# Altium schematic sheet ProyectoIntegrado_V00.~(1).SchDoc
size A4
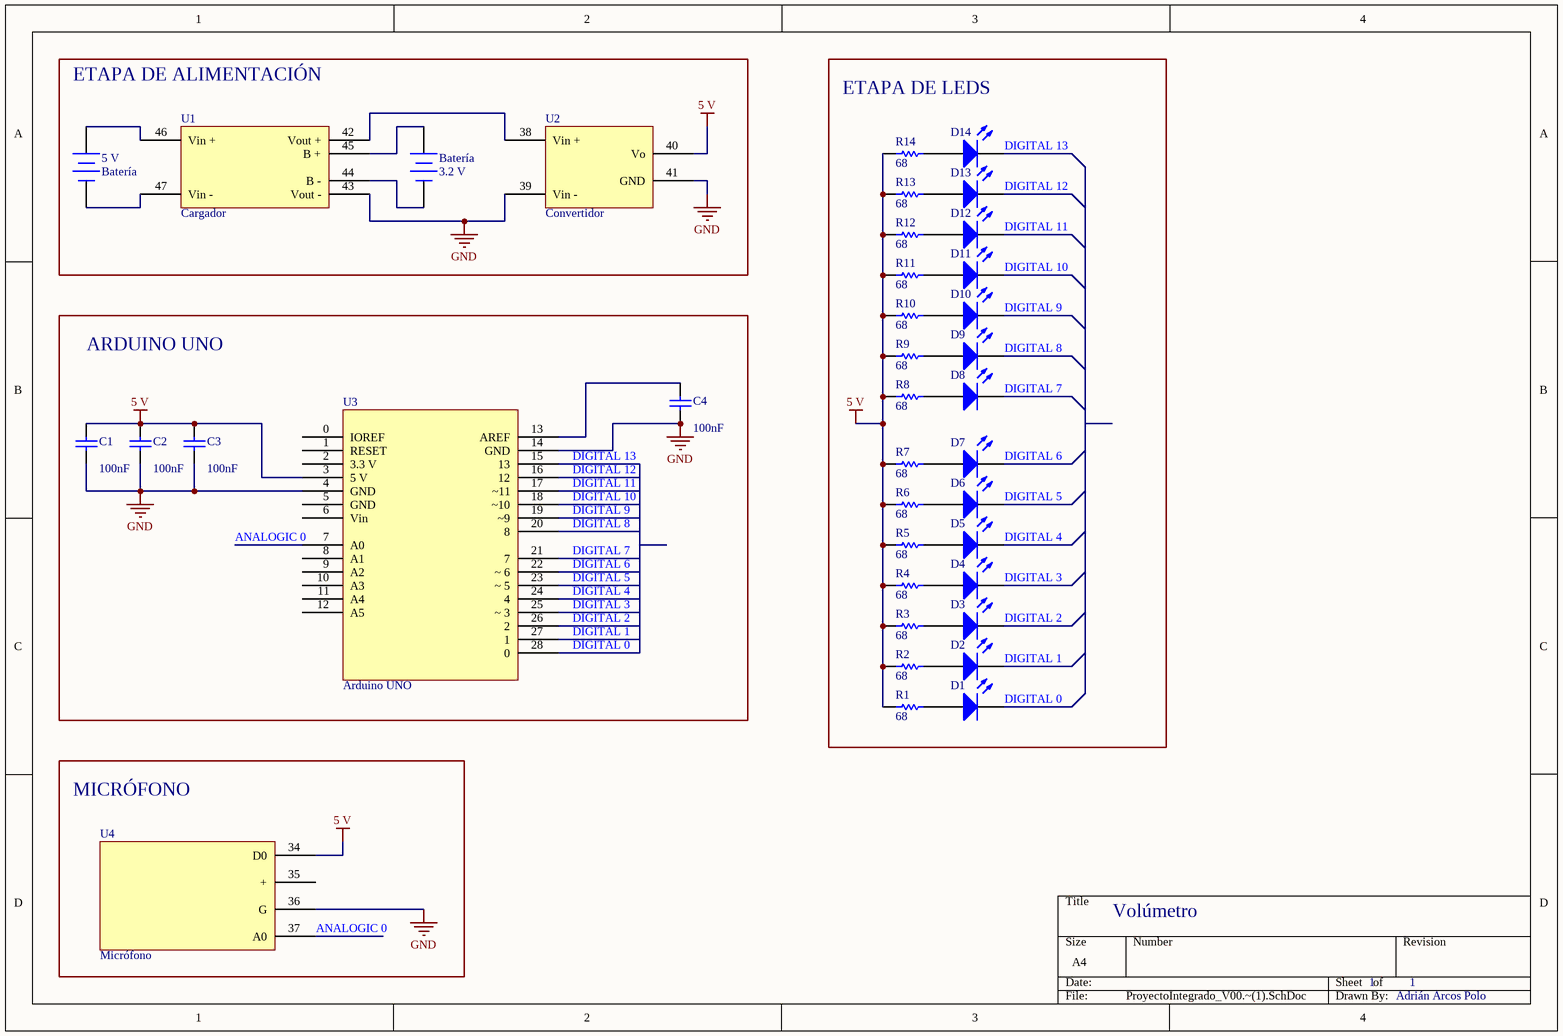
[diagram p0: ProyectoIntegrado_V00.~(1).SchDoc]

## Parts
5_V  Batería  [BAT-2]
Batería  3.2 V  [BAT-2]
C1  value 100nF  [RAD-0.3]  (hidden comment: Cap)
C2  value 100nF  [RAD-0.3]  (hidden comment: Cap)
C3  value 100nF  [RAD-0.3]  (hidden comment: Cap)
C4  value 100nF  [RAD-0.3]  (hidden comment: Cap)
D1  LED3  [3.5X2.8X1.9]  (value not drawn)
D2  LED3  [3.5X2.8X1.9]  (value not drawn)
D3  LED3  [3.5X2.8X1.9]  (value not drawn)
D4  LED3  [3.5X2.8X1.9]  (value not drawn)
D5  LED3  [3.5X2.8X1.9]  (value not drawn)
D6  LED3  [3.5X2.8X1.9]  (value not drawn)
D7  LED3  [3.5X2.8X1.9]  (value not drawn)
D8  LED3  [3.5X2.8X1.9]  (value not drawn)
D9  ED0  [LED-0]  (value not drawn)
D10  LED0  [LED-0]  (value not drawn)
D11  LED0  [LED-0]  (value not drawn)
D12  LED0  [LED-0]  (value not drawn)
D13  LED0  [LED-0]  (value not drawn)
D14  LED0  [LED-0]  (value not drawn)
R1  value 68  [AXIAL-0.3]  (hidden comment: Res1)
R2  value 68  [AXIAL-0.3]  (hidden comment: Res1)
R3  value 68  [AXIAL-0.3]  (hidden comment: Res1)
R4  value 68  [AXIAL-0.3]  (hidden comment: Res1)
R5  value 68  [AXIAL-0.3]  (hidden comment: Res1)
R6  value 68  [AXIAL-0.3]  (hidden comment: Res1)
R7  value 68  [AXIAL-0.3]  (hidden comment: Res1)
R8  value 68  [AXIAL-0.3]  (hidden comment: Res1)
R9  value 68  [AXIAL-0.3]  (hidden comment: Res1)
R10  value 68  [AXIAL-0.3]  (hidden comment: Res1)
R11  value 68  [AXIAL-0.3]  (hidden comment: Res1)
R12  value 68  [AXIAL-0.3]  (hidden comment: Res1)
R13  value 68  [AXIAL-0.3]  (hidden comment: Res1)
R14  value 68  [AXIAL-0.3]  (hidden comment: Res1)
U1  Cargador
U2  Convertidor
U3  Arduino UNO
U4  Micrófono

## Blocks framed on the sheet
ETAPA DE ALIMENTACIÓN: 5_V Batería U1 U2
ETAPA DE LEDS: D1-D14 R1-R14
ARDUINO UNO: C1-C4 U3
MICRÓFONO: U4

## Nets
5 V: C1.2 C2.2 C3.2 R1.2 R2.2 R3.2 R4.2 R5.2 R6.2 R7.2 R8.2 R9.2 R10.2 R11.2 R12.2 R13.2 R14.2 U2.40(Vo) U3.3(5_V) U4.34(D0)
GND: C1.1 C2.1 C3.1 C4.1 U1.43(Vout_-) U2.39(Vin_-) U2.41(GND) U3.4(GND) U3.14(GND) U4.36(G)
ANALOGIC 0: U3.7(A0) U4.37(A0)
DIGITAL 0: D1.2(K) U3.28(0)
DIGITAL 1: D2.2(K) U3.27(1)
DIGITAL 2: D3.2(K) U3.26(2)
DIGITAL 3: D4.2(K) U3.25(~_3)
DIGITAL 4: D5.2(K) U3.24(4)
DIGITAL 5: D6.2(K) U3.23(~_5)
DIGITAL 6: D7.2(K) U3.22(~_6)
DIGITAL 7: D8.2(K) U3.21(7)
DIGITAL 8: D9.2(K) U3.20(8)
DIGITAL 9: D10.2(K) U3.19(~9)
DIGITAL 10: D11.2(K) U3.18(~10)
DIGITAL 11: D12.2(K) U3.17(~11)
DIGITAL 12: D13.2(K) U3.16(12)
DIGITAL 13: D14.2(K) U3.15(13)
Net5_V_1: 5_V.1(+) U1.46(Vin_+)
Net5_V_2: 5_V.2(-) U1.47(Vin_-)
NetBatería_1: Batería.1(+) U1.45(B_+)
NetBatería_2: Batería.2(-) U1.44(B_-)
NetC4_2: C4.2 U3.13(AREF)
NetD1_1: D1.1(A) R1.1
NetD2_1: D2.1(A) R2.1
NetD3_1: D3.1(A) R3.1
NetD4_1: D4.1(A) R4.1
NetD5_1: D5.1(A) R5.1
NetD6_1: D6.1(A) R6.1
NetD7_1: D7.1(A) R7.1
NetD8_1: D8.1(A) R8.1
NetD9_1: D9.1(A) R9.1
NetD10_1: D10.1(A) R10.1
NetD11_1: D11.1(A) R11.1
NetD12_1: D12.1(A) R12.1
NetD13_1: D13.1(A) R13.1
NetD14_1: D14.1(A) R14.1
NetU1_42: U1.42(Vout_+) U2.38(Vin_+)

Not connected (* = marked no-connect by the designer): U3 0(IOREF) 1(RESET) 2(3.3_V) 5(GND) 6(Vin) 8(A1) 9(A2) 10(A3) 11(A4) 12(A5); U4 35(+)

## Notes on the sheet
- Volúmetro
- 1
- Adrián Arcos Polo

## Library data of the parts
5_V Batería = Battery: Multicell Battery
C1-C4 = Cap: Capacitor
D1-D8 = LED3: Typical BLUE SiC LED
D9-D14 = LED0: Typical INFRARED GaAs LED
R1-R14 = Res1: Resistor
